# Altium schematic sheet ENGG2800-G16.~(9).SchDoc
size A3
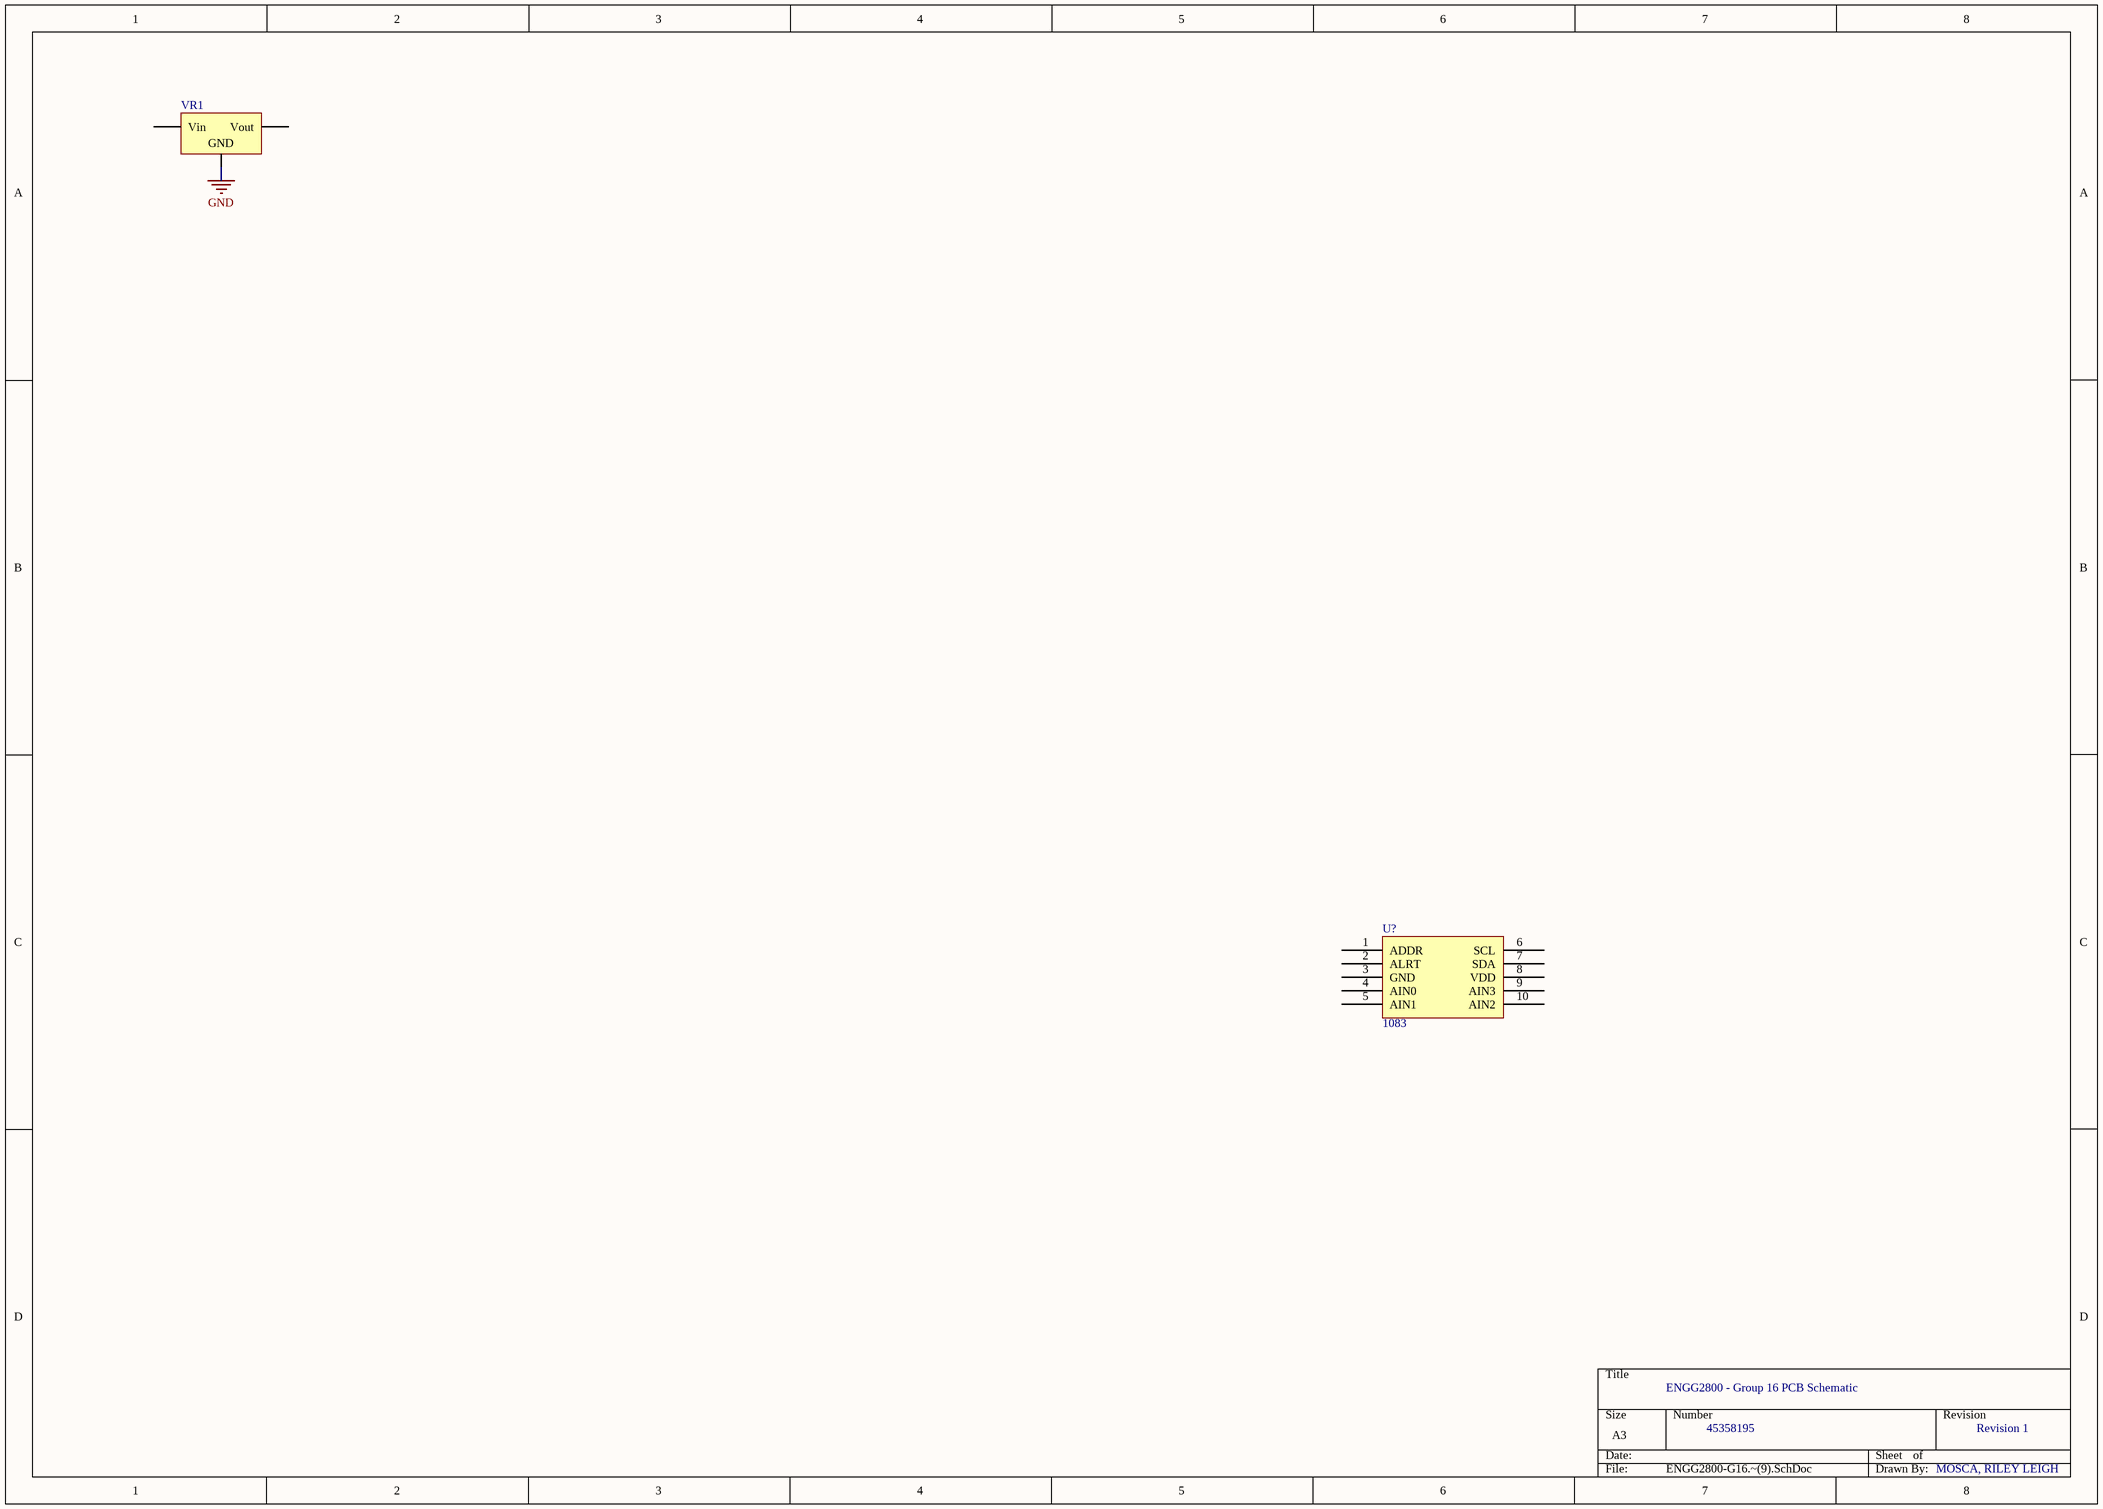
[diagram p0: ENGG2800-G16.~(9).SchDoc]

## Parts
U?  1083
VR1  Volt Reg  [D2PAK_N]  (value not drawn)

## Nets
GND: VR1.2(GND)

Not connected (* = marked no-connect by the designer): U? 1(ADDR) 2(ALRT) 3(GND) 4(AIN0) 5(AIN1) 6(SCL) 7(SDA) 8(VDD) 9(AIN3) 10(AIN2); VR1 1(Vin) 3(Vout)

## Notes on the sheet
- ENGG2800 - Group 16 PCB Schematic
- 45358195
- Revision 1
- MOSCA, RILEY LEIGH

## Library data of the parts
U? = 1083: EVAL BOARD ADS1115 16-BIT ADC; Manufacturer: Adafruit Industries; Number of Bits: 12; Evaluation Kit: Yes; Number of A/D Converters: 1; Sampling Rate: 3300S/s; Interface: I2C,Serial
VR1 = Volt Reg: Voltage Regulator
